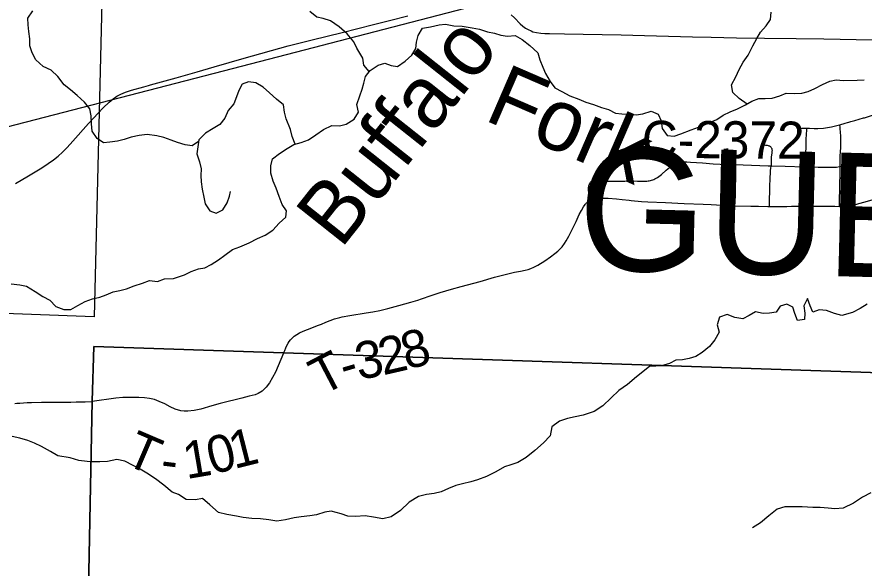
# Model space of a CAD drawing. Extents: x 0 to 34, y 0 to 22.
# Drawn here: x 5.291 to 6.588, y 19.271 to 20.115 of the extents above; entities that cross this region are included whole.
import ezdxf

# ---------------------------------------------------------------- set-up
doc = ezdxf.new("R2010")
doc.units = 0
for name, color, linetype in [('GM_X_Corporation', 7, 'Continuous'), ('GM_X_County_Road_Text', 7, 'Continuous'), ('GM_X_County_Text', 7, 'Continuous'), ('GM_X_Minor_River', 7, 'Continuous'), ('GM_X_Minor_River_Text', 7, 'Continuous'), ('GM_X_Rail_Line', 7, 'Continuous'), ('GM_X_State_Route', 7, 'Continuous'), ('GM_X_Township_Road', 7, 'Continuous'), ('GM_X_Township_Road_Text', 7, 'Continuous')]:
    doc.layers.add(name, color=color, linetype=linetype)

msp = doc.modelspace()

# ---------------------------------------------------------------- linework, layer by layer
at = {"layer": 'GM_X_Corporation'}
msp.add_lwpolyline([(5.4344, 20.6525), (5.4328, 20.6183), (5.4095, 19.6556), (4.3939, 19.6935), (4.4032, 20.6929)], close=True, dxfattribs=at)
for points in [[(5.3543, 16.3597), (5.3699, 17.5116), (5.3717, 17.6123), (5.3798, 17.8448), (5.3967, 19.0299), (5.4062, 19.5263), (5.4087, 19.6104), (5.6993, 19.6004), (6.6444, 19.5688), (7.0794, 19.5596), (7.3097, 19.5503), (7.9584, 19.5358), (7.9795, 19.5354), (8.4033, 19.5268)], [(8.4033, 19.5268), (7.9795, 19.5354), (7.9584, 19.5358), (7.3097, 19.5503), (7.0794, 19.5596), (6.6444, 19.5688), (5.6993, 19.6004), (5.4087, 19.6104), (5.4062, 19.5263), (5.3967, 19.0299), (5.3798, 17.8448), (5.3717, 17.6123), (5.3699, 17.5116), (5.3543, 16.3597)], [(8.4033, 19.5268), (7.9795, 19.5354), (7.9584, 19.5358), (7.3097, 19.5503), (7.0794, 19.5596), (6.6444, 19.5688), (5.6993, 19.6004), (5.4087, 19.6104), (5.4062, 19.5263), (5.3967, 19.0299), (5.3798, 17.8448), (5.3717, 17.6123), (5.3699, 17.5116), (5.3543, 16.3597)], [(5.3967, 19.0299), (5.4062, 19.5263), (5.4087, 19.6104), (5.6993, 19.6004), (6.6444, 19.5688), (7.0794, 19.5596), (7.3097, 19.5503), (7.9584, 19.5358), (7.9795, 19.5354), (8.4033, 19.5268)]]:
    msp.add_lwpolyline(points, dxfattribs=at)
at = {"layer": 'GM_X_Minor_River'}
for points in [[(5.5693, 19.9242), (5.5595, 19.9177), (5.5489, 19.9191), (5.5368, 19.9227), (5.5273, 19.9264), (5.5159, 19.9305), (5.5053, 19.933), (5.4902, 19.9347), (5.4781, 19.9335), (5.466, 19.9307), (5.4551, 19.9272), (5.4449, 19.9248), (5.4332, 19.9231), (5.4234, 19.9223), (5.4139, 19.9286), (5.4062, 19.9399), (5.4053, 19.9513), (5.4049, 19.9634), (5.4025, 19.9743), (5.3945, 19.9845), (5.3834, 19.9946), (5.3728, 20.0032), (5.3632, 20.0111), (5.3537, 20.0235), (5.3434, 20.0332), (5.3312, 20.0391), (5.3198, 20.0493), (5.3141, 20.0598), (5.3106, 20.0704), (5.3105, 20.0814), (5.3092, 20.0927), (5.3084, 20.1026), (5.3075, 20.1132), (5.3154, 20.1242)], [(5.8307, 20.0311), (5.8223, 20.0409), (5.821, 20.0519), (5.8118, 20.067), (5.8068, 20.0768), (5.7969, 20.0892), (5.7847, 20.0996), (5.7714, 20.109), (5.76, 20.1126), (5.7502, 20.1144), (5.7395, 20.1234)], [(6.4093, 19.9815), (6.3973, 19.9902), (6.3877, 19.9992), (6.3854, 20.0109), (6.3921, 20.0231), (6.3973, 20.0342), (6.4032, 20.0456), (6.4111, 20.0563), (6.4181, 20.0707), (6.4244, 20.0818), (6.4297, 20.0917), (6.4383, 20.1013), (6.4454, 20.1108), (6.4464, 20.1222)], [(5.3956, 19.6791), (5.4066, 19.683), (5.4179, 19.6858), (5.4277, 19.6893), (5.4382, 19.694), (5.4484, 19.696), (5.459, 19.6987), (5.4703, 19.703), (5.4835, 19.7073), (5.494, 19.7112), (5.5061, 19.7099), (5.517, 19.7138), (5.531, 19.7143), (5.5476, 19.7201), (5.5578, 19.7248), (5.5691, 19.7291), (5.5789, 19.7307), (5.5887, 19.7357), (5.5996, 19.7427), (5.6093, 19.7503), (5.621, 19.7588), (5.6323, 19.7627), (5.6466, 19.7689), (5.6594, 19.7755), (5.6711, 19.7806), (5.6831, 19.7883), (5.6928, 19.799), (5.703, 19.8085), (5.704, 19.818), (5.6971, 19.8278), (5.6925, 19.8399), (5.6878, 19.8527), (5.6832, 19.8633), (5.6797, 19.8754), (5.68, 19.8871), (5.6825, 19.8974), (5.693, 19.9058), (5.7051, 19.9135), (5.7152, 19.9193), (5.7261, 19.9228), (5.7378, 19.9267), (5.7487, 19.9344), (5.7604, 19.9425), (5.7735, 19.9487), (5.7849, 19.9481), (5.7951, 19.9505), (5.8075, 19.9582), (5.8142, 19.9689), (5.8118, 19.9806), (5.8162, 19.9939), (5.8196, 20.0041), (5.8225, 20.0137), (5.8251, 20.0235), (5.8322, 20.0331), (5.8442, 20.0408), (5.8544, 20.0439), (5.8642, 20.0406), (5.8741, 20.0388), (5.8857, 20.0469), (5.8958, 20.0561), (5.9018, 20.0664), (5.9028, 20.0763), (5.9054, 20.0865), (5.9121, 20.0976), (5.9246, 20.0996), (5.9378, 20.1028), (5.9476, 20.1036), (5.9601, 20.1011), (5.9729, 20.1009), (5.9881, 20.098), (5.9994, 20.0959), (6.0119, 20.0922), (6.0226, 20.09), (6.032, 20.0867), (6.0423, 20.0853), (6.054, 20.0862), (6.065, 20.0803), (6.0764, 20.0709), (6.0886, 20.06), (6.0917, 20.0491), (6.0963, 20.0382), (6.1006, 20.0284), (6.1079, 20.0159), (6.1151, 20.0062), (6.1258, 20.0006), (6.1376, 19.9939), (6.1516, 19.9887), (6.1622, 19.9843), (6.1743, 19.9806), (6.1865, 19.9762), (6.1971, 19.9729), (6.2077, 19.9677), (6.2175, 19.9667), (6.2293, 19.9661), (6.2395, 19.965), (6.2497, 19.9667), (6.2625, 19.9706), (6.2731, 19.9658), (6.2777, 19.9556), (6.279, 19.9439), (6.287, 19.9333)], [(5.7172, 19.9199), (5.7125, 19.9318), (5.7101, 19.9424), (5.7035, 19.959), (5.7008, 19.9692), (5.6992, 19.9801), (5.6885, 19.9887), (5.6779, 19.9989), (5.668, 20.0071), (5.6569, 20.0142), (5.6456, 20.0156), (5.6358, 20.0117), (5.631, 20.0022), (5.6273, 19.9923), (5.6232, 19.982), (5.6146, 19.9717), (5.6094, 19.9599), (5.6015, 19.9503), (5.5914, 19.9441), (5.5797, 19.9368), (5.5696, 19.9269), (5.5682, 19.9159), (5.5664, 19.9052), (5.5707, 19.8932), (5.5734, 19.8822), (5.5727, 19.8723), (5.5732, 19.8625), (5.5748, 19.8511), (5.5772, 19.839), (5.5795, 19.8285), (5.5864, 19.8179), (5.5959, 19.8146), (5.6065, 19.8196), (5.6132, 19.8303), (5.6165, 19.8402), (5.6183, 19.8478)], [(6.287, 19.9333), (6.2976, 19.9323), (6.3078, 19.9358), (6.3236, 19.9421), (6.3406, 19.9483), (6.3519, 19.9534), (6.3632, 19.958), (6.3729, 19.9642), (6.3835, 19.9696), (6.3948, 19.9739), (6.4068, 19.9801), (6.4166, 19.9859), (6.4271, 19.9898), (6.437, 19.9899), (6.4475, 19.9907), (6.4596, 19.9943), (6.4694, 19.9982), (6.4815, 19.9975), (6.4932, 19.998), (6.503, 20.0008), (6.5132, 20.0051), (6.5249, 20.0113), (6.5362, 20.0167), (6.546, 20.0183), (6.5569, 20.0177), (6.5781, 20.0179), (6.5887, 20.0184)], [(5.282, 19.7063), (5.2952, 19.7046), (5.3055, 19.7028), (5.3191, 19.6946), (5.3305, 19.6868), (5.3412, 19.6812), (5.3507, 19.6715), (5.3628, 19.667), (5.3734, 19.6668), (5.384, 19.6729), (5.3956, 19.6791)], [(6.5932, 19.6748), (6.5823, 19.6686), (6.5706, 19.6624), (6.5544, 19.6577), (6.543, 19.6606), (6.5309, 19.6654), (6.5199, 19.6664), (6.5098, 19.6629), (6.5059, 19.6727), (6.502, 19.6837), (6.4964, 19.6726), (6.4977, 19.6613), (6.497, 19.6514), (6.4864, 19.6498), (6.4826, 19.6607), (6.4794, 19.6706), (6.47, 19.675), (6.4598, 19.6722), (6.4538, 19.6627), (6.4436, 19.6611), (6.4338, 19.6606), (6.4224, 19.6631), (6.4126, 19.6577), (6.4029, 19.6527), (6.3904, 19.6545), (6.3786, 19.6593), (6.3673, 19.655), (6.3633, 19.6432), (6.3664, 19.6322), (6.3597, 19.6204), (6.3518, 19.6101), (6.3406, 19.6009), (6.3308, 19.5951), (6.3206, 19.592), (6.3104, 19.5896), (6.3002, 19.5891), (6.2904, 19.5841), (6.2784, 19.5806), (6.2697, 19.5801), (6.2597, 19.5798)], [(6.2597, 19.5798), (6.2401, 19.5635), (6.2261, 19.5521), (6.2128, 19.5426), (6.2011, 19.5317), (6.1886, 19.5192), (6.1749, 19.5105), (6.1583, 19.5052), (6.1458, 19.5025), (6.1341, 19.4999), (6.122, 19.4958), (6.1102, 19.487), (6.1079, 19.4734), (6.0973, 19.4628), (6.0841, 19.4511), (6.0708, 19.4401), (6.058, 19.4325), (6.0477, 19.4288), (6.0379, 19.4257), (6.0246, 19.4185), (6.0103, 19.411), (5.9966, 19.4061), (5.9861, 19.403), (5.9732, 19.4), (5.9634, 19.3974), (5.952, 19.3925), (5.941, 19.3876), (5.9301, 19.3853), (5.9183, 19.3838), (5.9062, 19.3804), (5.8918, 19.3717), (5.8786, 19.3592), (5.8642, 19.3494), (5.8513, 19.3464), (5.837, 19.3487), (5.8241, 19.3509), (5.8097, 19.3498), (5.798, 19.3506), (5.7874, 19.354), (5.7723, 19.3578), (5.7625, 19.3567), (5.7496, 19.3522), (5.7398, 19.3507), (5.7262, 19.3492), (5.7156, 19.3477), (5.7023, 19.345), (5.6891, 19.3428), (5.6766, 19.3447), (5.6641, 19.3462), (5.6509, 19.3466), (5.6373, 19.3481), (5.6271, 19.3504), (5.6127, 19.3531), (5.5995, 19.3562), (5.5863, 19.3675), (5.5753, 19.3774), (5.5644, 19.3755), (5.55, 19.3759), (5.5383, 19.3835), (5.5285, 19.3873), (5.516, 19.3976), (5.5032, 19.4075), (5.49, 19.4162), (5.4798, 19.4226), (5.4692, 19.428), (5.4563, 19.4348), (5.4439, 19.4371), (5.4299, 19.4341), (5.4178, 19.4337), (5.4053, 19.4337), (5.3986, 19.4343)], [(5.3986, 19.4343), (5.3859, 19.4357), (5.3724, 19.4398), (5.3538, 19.443), (5.3424, 19.4494), (5.3288, 19.4572), (5.3181, 19.4624), (5.3079, 19.466), (5.2954, 19.4697), (5.2836, 19.4726)], [(6.599, 19.386), (6.5861, 19.3796), (6.5721, 19.3705), (6.5566, 19.3625), (6.5437, 19.3618), (6.5335, 19.3626), (6.521, 19.3637), (6.5101, 19.3637), (6.4938, 19.3645), (6.4813, 19.3645), (6.467, 19.3649), (6.4552, 19.3612), (6.4424, 19.3509), (6.4299, 19.3403), (6.4174, 19.3324)]]:
    msp.add_lwpolyline(points, dxfattribs=at)
at = {"layer": 'GM_X_Rail_Line'}
msp.add_lwpolyline([(7.1041, 20.4576), (6.548, 20.2811), (6.4552, 20.2522), (5.6204, 20.0355), (5.1742, 19.9198), (4.9387, 19.8589), (4.9007, 19.8493), (4.8622, 19.8368), (4.8204, 19.8197), (4.7961, 19.8057), (4.7682, 19.7883), (4.6322, 19.6788), (3.9277, 19.0962), (3.874, 19.0476), (3.8339, 19.0097), (3.7908, 18.9611), (3.75, 18.9158), (3.7169, 18.8748), (3.6829, 18.8279), (3.1625, 18.0833)], dxfattribs=at)
at = {"layer": 'GM_X_State_Route'}
for points in [[(5.2889, 19.8599), (5.3087, 19.8717), (5.3289, 19.8839), (5.3388, 19.8903), (5.3468, 19.896), (5.354, 19.9018), (5.3609, 19.908), (5.3679, 19.915), (5.3767, 19.9246), (5.4006, 19.9516), (5.4154, 19.9676), (5.4232, 19.9756), (5.4322, 19.9842), (5.4384, 19.9896), (5.4441, 19.9935), (5.4503, 19.9968), (5.4572, 19.9995), (5.4667, 20.0026), (5.4853, 20.0078), (5.4925, 20.0099), (5.4954, 20.0108), (5.5349, 20.0218), (5.5672, 20.0309), (5.5929, 20.0383), (5.6388, 20.0517), (5.7065, 20.0704), (5.7432, 20.0799), (5.7891, 20.0912), (5.8132, 20.0972), (5.8373, 20.1033), (5.8614, 20.1094), (5.8897, 20.1165)], [(6.0482, 20.1181), (6.0532, 20.1134), (6.0618, 20.1045), (6.0659, 20.1008), (6.0699, 20.0979), (6.0741, 20.0954), (6.0785, 20.0934), (6.0813, 20.0923), (6.0866, 20.0909), (6.0933, 20.09), (6.0994, 20.0896), (6.1069, 20.0894), (6.1299, 20.0889), (6.1584, 20.0884), (6.2162, 20.0875), (6.2523, 20.0865), (6.3256, 20.0844), (6.3541, 20.0837), (6.3933, 20.0831), (6.4361, 20.0823), (6.4846, 20.0817), (6.5268, 20.0814), (6.6014, 20.0799)]]:
    msp.add_lwpolyline(points, dxfattribs=at)
at = {"layer": 'GM_X_Township_Road'}
for points in [[(6.5515, 19.9497), (6.5595, 19.9522), (6.5629, 19.9532), (6.5652, 19.9539), (6.5682, 19.9547), (6.5741, 19.9563), (6.5875, 19.9602), (6.5893, 19.9606), (6.5968, 19.9631), (6.6096, 19.9668)], [(6.4927, 19.9444), (6.4939, 19.9445), (6.4957, 19.9445), (6.501, 19.9446)], [(6.4988, 19.8854), (6.4988, 19.8897), (6.499, 19.9015), (6.4996, 19.9145), (6.4999, 19.9264), (6.5001, 19.9363), (6.5006, 19.9406), (6.501, 19.9446)], [(6.501, 19.9446), (6.5022, 19.9445), (6.5051, 19.9446), (6.5123, 19.9442), (6.5179, 19.9441), (6.5265, 19.9447), (6.5327, 19.9454), (6.5388, 19.9466), (6.5507, 19.9496), (6.5515, 19.9497)], [(6.5517, 19.8859), (6.5517, 19.8905), (6.5519, 19.8986), (6.5521, 19.9023), (6.5525, 19.9085), (6.5528, 19.9147), (6.5531, 19.9208), (6.5531, 19.9263), (6.5529, 19.9287), (6.5529, 19.9311), (6.5527, 19.9344), (6.5526, 19.9364), (6.5518, 19.9455), (6.5515, 19.9497)], [(6.4334, 19.9188), (6.4355, 19.9188), (6.4377, 19.9187), (6.4389, 19.9186), (6.4402, 19.9184), (6.4416, 19.9181), (6.4427, 19.9177), (6.4435, 19.9173), (6.4443, 19.9169), (6.445, 19.9163), (6.4457, 19.9156), (6.4464, 19.9148), (6.4468, 19.9141), (6.4471, 19.9134), (6.4473, 19.9128)], [(6.5517, 19.8859), (6.5579, 19.8872), (6.5729, 19.8912), (6.5962, 19.898), (6.6175, 19.9044), (6.6342, 19.9091), (6.6504, 19.9134), (6.666, 19.9178), (6.672, 19.9195)], [(6.4473, 19.9128), (6.4474, 19.912), (6.4475, 19.911), (6.4475, 19.9103), (6.4474, 19.9094), (6.4474, 19.9085), (6.4471, 19.9062), (6.4464, 19.9004), (6.4461, 19.8981), (6.446, 19.8956), (6.4461, 19.887)], [(6.2929, 19.8862), (6.2953, 19.8877), (6.2965, 19.8884), (6.2978, 19.8891), (6.2991, 19.8897), (6.3003, 19.8904), (6.3018, 19.8911), (6.3034, 19.8917), (6.3049, 19.8922), (6.3062, 19.8924), (6.3083, 19.8927), (6.3098, 19.8928), (6.3121, 19.8929), (6.3138, 19.893), (6.3168, 19.893), (6.3228, 19.8926), (6.3408, 19.8912), (6.3575, 19.8899), (6.3681, 19.8895), (6.378, 19.8891), (6.3903, 19.8887), (6.3923, 19.8887)], [(6.167, 19.8568), (6.1674, 19.858), (6.1682, 19.8595), (6.169, 19.8608), (6.1697, 19.8619), (6.1705, 19.8627), (6.1712, 19.8634), (6.172, 19.8638), (6.1733, 19.8642), (6.176, 19.8642), (6.1779, 19.8643), (6.1859, 19.864), (6.1883, 19.8639), (6.1914, 19.8637), (6.1938, 19.8636), (6.1975, 19.8635), (6.2044, 19.8632), (6.2142, 19.8632), (6.2222, 19.8634), (6.2253, 19.8637), (6.2308, 19.8638), (6.2414, 19.8634), (6.2488, 19.8632), (6.2557, 19.8635), (6.2577, 19.8637), (6.2594, 19.864), (6.2612, 19.8643), (6.263, 19.8648), (6.2647, 19.8654), (6.2665, 19.8661), (6.2682, 19.867), (6.2698, 19.8678), (6.2719, 19.869), (6.274, 19.8704), (6.2784, 19.8738), (6.2854, 19.88), (6.2905, 19.8845), (6.2929, 19.8862)], [(6.3906, 19.8256), (6.3909, 19.8305), (6.3912, 19.8346), (6.3914, 19.8389), (6.3914, 19.847), (6.3915, 19.8489), (6.3915, 19.8527), (6.3916, 19.8576), (6.3919, 19.8651), (6.392, 19.8669), (6.3919, 19.8688), (6.3919, 19.8707), (6.3919, 19.8731), (6.392, 19.8771), (6.3921, 19.8795), (6.3923, 19.8887)], [(6.3923, 19.8887), (6.4033, 19.8884), (6.4414, 19.8871), (6.4461, 19.887)], [(6.4437, 19.8246), (6.4438, 19.8294), (6.4438, 19.8324), (6.4438, 19.8386), (6.4439, 19.8448), (6.4442, 19.8522), (6.4448, 19.8707), (6.445, 19.8741), (6.4452, 19.8775), (6.4454, 19.8801), (6.4457, 19.883), (6.4461, 19.887)], [(6.4461, 19.887), (6.4674, 19.8863), (6.4966, 19.8854), (6.4988, 19.8854)], [(6.4988, 19.8854), (6.5083, 19.8851), (6.5183, 19.885), (6.5282, 19.8848), (6.5418, 19.8847), (6.5462, 19.885), (6.5506, 19.8856), (6.5517, 19.8859)], [(6.5509, 19.8247), (6.5508, 19.8296), (6.5507, 19.8364), (6.5513, 19.8499), (6.5514, 19.8554), (6.5515, 19.8615), (6.5519, 19.8714), (6.5517, 19.88), (6.5517, 19.8859)], [(6.1668, 19.8326), (6.1668, 19.8386), (6.1668, 19.8411), (6.1668, 19.8447), (6.1665, 19.8508), (6.1666, 19.8539), (6.1667, 19.8553), (6.167, 19.8568)], [(6.5509, 19.8247), (6.5528, 19.8247), (6.557, 19.8246), (6.5606, 19.825), (6.5638, 19.8254), (6.5677, 19.8261), (6.5719, 19.8269), (6.5743, 19.8276), (6.5772, 19.8283), (6.5805, 19.8293), (6.5901, 19.8318), (6.6061, 19.8365), (6.611, 19.8378), (6.6216, 19.8412), (6.6333, 19.8448), (6.6483, 19.8488), (6.6614, 19.8523), (6.6698, 19.8547), (6.6745, 19.8563), (6.6886, 19.8613), (6.6933, 19.863)], [(5.6995, 19.5998), (5.7012, 19.604), (5.7029, 19.608), (5.704, 19.6108), (5.7062, 19.6152), (5.7077, 19.6177), (5.71, 19.6206), (5.7125, 19.6232), (5.7157, 19.6259), (5.7197, 19.6287), (5.724, 19.6312), (5.7295, 19.6338), (5.7428, 19.639), (5.7515, 19.6424), (5.7573, 19.6446), (5.7642, 19.6473), (5.7705, 19.6499), (5.7774, 19.6525), (5.7815, 19.6538), (5.7853, 19.6548), (5.7893, 19.6557), (5.8008, 19.6577), (5.8259, 19.6615), (5.8363, 19.6631), (5.8467, 19.6652), (5.8593, 19.6683), (5.8759, 19.6729), (5.8943, 19.6779), (5.905, 19.681), (5.9107, 19.683), (5.9253, 19.6882), (5.9394, 19.6929), (5.9566, 19.6981), (5.9716, 19.7021), (5.9812, 19.7046), (6.0004, 19.7098), (6.0225, 19.7162), (6.0471, 19.7224), (6.0531, 19.7238), (6.0622, 19.7254), (6.0696, 19.7269), (6.0739, 19.728), (6.078, 19.7295), (6.0826, 19.7316), (6.0887, 19.7349), (6.0993, 19.7414), (6.1081, 19.7473), (6.1151, 19.7525), (6.1195, 19.7561), (6.1231, 19.7597), (6.1259, 19.763), (6.1296, 19.7681), (6.132, 19.7718), (6.1364, 19.7793), (6.141, 19.7881), (6.1474, 19.8016), (6.1523, 19.8122), (6.1557, 19.8187), (6.1587, 19.8241), (6.1611, 19.8276), (6.162, 19.8288), (6.1626, 19.8294), (6.1631, 19.83), (6.164, 19.8308), (6.1646, 19.8313), (6.1652, 19.8318), (6.1658, 19.8321), (6.1668, 19.8326)], [(6.1668, 19.8326), (6.168, 19.8332), (6.1705, 19.8344), (6.1733, 19.8353), (6.1748, 19.8358), (6.1768, 19.8363), (6.1789, 19.8366), (6.1815, 19.837), (6.1831, 19.8372), (6.184, 19.8373), (6.1876, 19.8376), (6.1894, 19.8376), (6.1908, 19.8376), (6.1934, 19.8375), (6.1966, 19.8374), (6.2095, 19.8362), (6.218, 19.8353), (6.2287, 19.8342)], [(6.2287, 19.8342), (6.2316, 19.8338), (6.2478, 19.8324), (6.2571, 19.8319), (6.2844, 19.8305), (6.3129, 19.8292), (6.3421, 19.8281), (6.3545, 19.8277), (6.3705, 19.8266), (6.381, 19.8259), (6.3906, 19.8256)], [(6.3906, 19.8256), (6.4152, 19.8252), (6.427, 19.8249), (6.4412, 19.8246), (6.4437, 19.8246)], [(6.4437, 19.8246), (6.4573, 19.8246), (6.4635, 19.8246), (6.4654, 19.8246), (6.4703, 19.8248), (6.4775, 19.8252), (6.48, 19.8252), (6.4824, 19.8252), (6.4842, 19.8251), (6.4867, 19.8252), (6.4885, 19.8251), (6.4977, 19.8251), (6.5082, 19.8251), (6.5175, 19.8251), (6.5206, 19.8251), (6.5231, 19.8251), (6.528, 19.825), (6.5349, 19.8249), (6.5404, 19.8249), (6.5435, 19.825), (6.5509, 19.8247)], [(5.6995, 19.5998), (5.687, 19.5709), (5.6778, 19.5547), (5.6729, 19.5477), (5.6666, 19.5419), (5.6603, 19.5383), (5.6557, 19.5364), (5.6467, 19.534), (5.6355, 19.5311), (5.6251, 19.5286), (5.6147, 19.5261), (5.6025, 19.5227), (5.5896, 19.5192), (5.5727, 19.5144), (5.5626, 19.5124), (5.5526, 19.5111), (5.5473, 19.511), (5.5421, 19.5117), (5.5333, 19.5143), (5.5259, 19.5177), (5.5174, 19.5224), (5.5086, 19.5262), (5.5017, 19.5288), (5.4942, 19.5306), (5.4866, 19.5317), (5.4777, 19.5323), (5.4626, 19.5323), (5.4532, 19.532), (5.4426, 19.5309), (5.4064, 19.5258)], [(5.2879, 19.5229), (5.291, 19.5232), (5.2953, 19.5235), (5.3064, 19.5244), (5.3132, 19.5246), (5.3287, 19.5248), (5.348, 19.5248), (5.3585, 19.5248), (5.366, 19.5249), (5.3734, 19.5251), (5.3819, 19.5253), (5.3854, 19.5254), (5.389, 19.5253), (5.3953, 19.5254), (5.4064, 19.5258)]]:
    msp.add_lwpolyline(points, dxfattribs=at)

# ---------------------------------------------------------------- texts
at = {"layer": 'GM_X_County_Road_Text'}
msp.add_text('C-2372', height=0.05682, rotation=359.6397, dxfattribs=at).set_placement((6.248, 19.8992))
at = {"layer": 'GM_X_County_Text'}
msp.add_text('GUERNSEY COUNTY', height=0.189394, rotation=358.543, dxfattribs=at).set_placement((6.1485, 19.728))
at = {"layer": 'GM_X_Minor_River_Text'}
for s, rotation, p in [('Buffalo', 51.577, (5.787, 19.7581)), ('Fork', 336.5812, (6.0044, 19.9579))]:
    msp.add_text(s, height=0.09469, rotation=rotation, dxfattribs=at).set_placement(p)
at = {"layer": 'GM_X_Township_Road_Text'}
for s, rotation, p in [('8', 15.1423, (5.888, 19.5743)), ('3', 10.2092, (5.8143, 19.559)), ('2', 13.0062, (5.8517, 19.5659)), ('T', 27.5751, (5.7585, 19.5343)), ('-', 16.3598, (5.7935, 19.5528)), ('T', 336.8695, (5.4536, 19.4307)), ('0', 14.1375, (5.5898, 19.4139)), ('1', 14.1395, (5.6237, 19.4224)), ('1', 9.6725, (5.5505, 19.407)), ('-', 352.9181, (5.5093, 19.4095))]:
    msp.add_text(s, height=0.0568, rotation=rotation, dxfattribs=at).set_placement(p)

doc.saveas('drawing.dxf')
